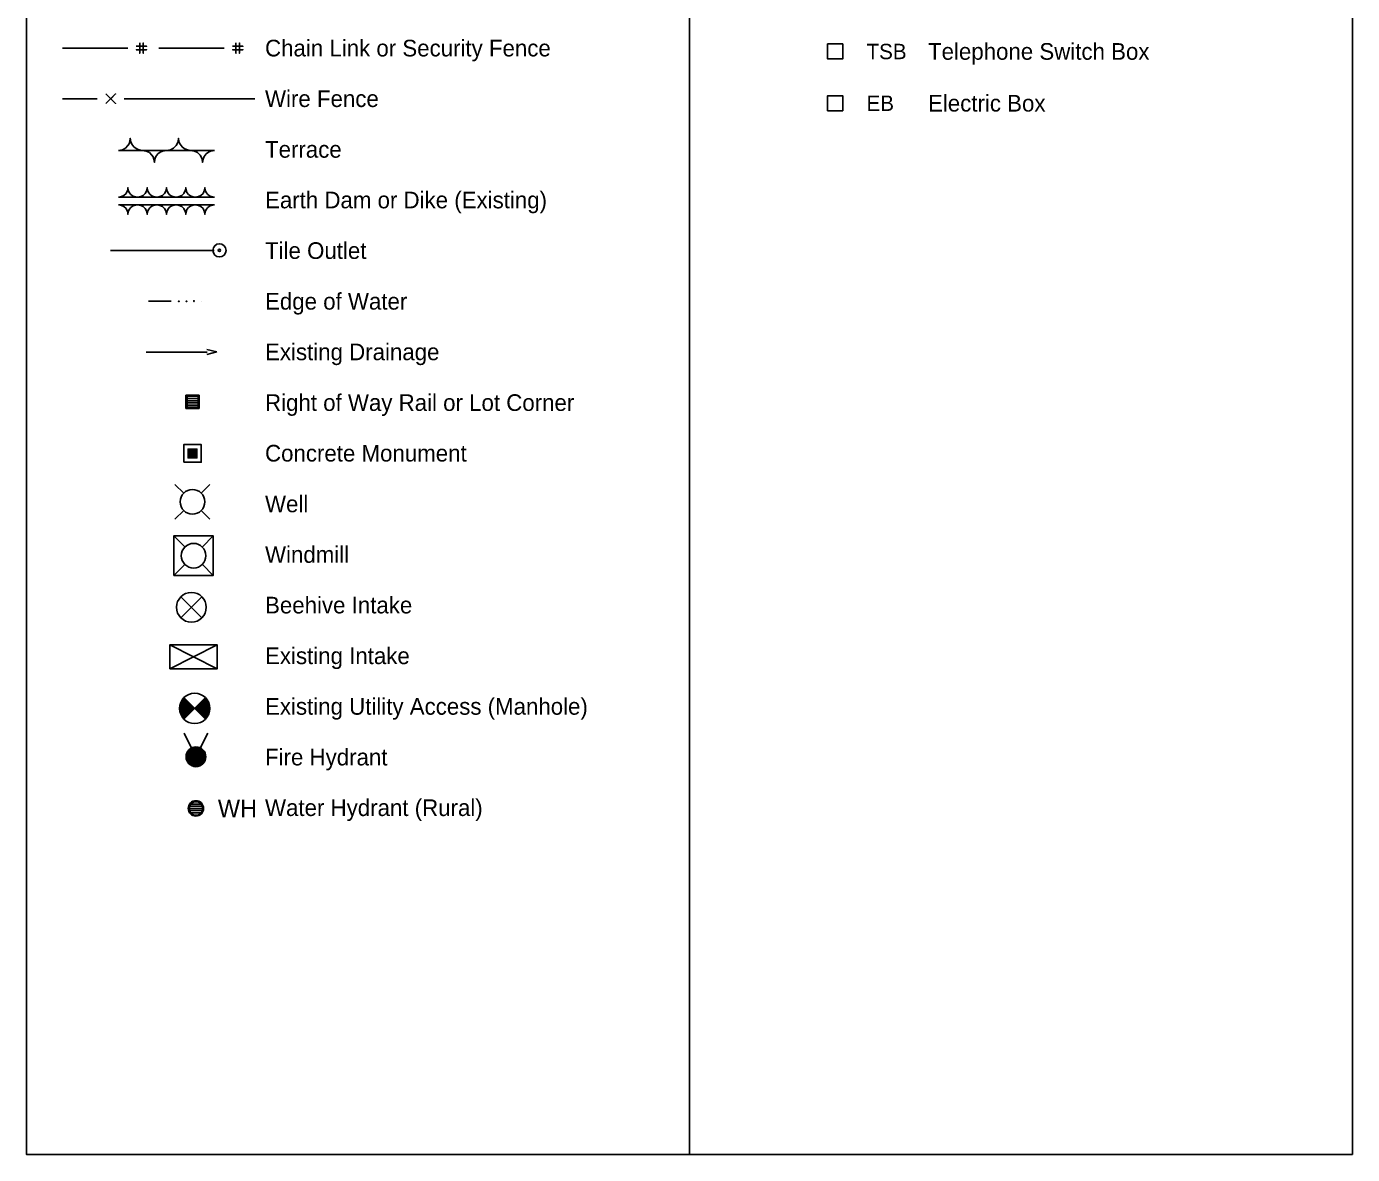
# Model space of a CAD drawing. Extents: x 6082259 to 6083454, y 5964102 to 5966092.
# Drawn here: x 6082259 to 6083454, y 5964102 to 5965119 of the extents above; entities that cross this region are included whole.
import ezdxf

# ---------------------------------------------------------------- set-up
doc = ezdxf.new("R2010")
doc.units = 0
for name, color, linetype in [('Default', 7, 'Continuous'), ('dsnTextShtTitle', 7, 'Continuous'), ('ShtPlotIdentification', 7, 'Continuous')]:
    doc.layers.add(name, color=color, linetype=linetype)

msp = doc.modelspace()

# ---------------------------------------------------------------- linework, layer by layer
at = {"layer": 'Default'}
for points in [[(6082259, 5966092.2), (6082856.5, 5966092.2), (6082856.5, 5964102.2), (6082259, 5964102.2)], [(6082856.5, 5966092.2), (6083454, 5966092.2), (6083454, 5964102.2), (6082856.5, 5964102.2)]]:
    msp.add_lwpolyline(points, close=True, dxfattribs=at)
at = {"layer": 'ShtPlotIdentification'}
for p, q in [((6082334.7, 5964916.8), (6082428.3, 5964916.8)), ((6082369, 5964871.1), (6082389.5, 5964871.1)), ((6082410, 5964871.1), (6082410, 5964871.1)), ((6082417, 5964871.3), (6082417, 5964871.3)), ((6082367, 5964825.4), (6082421.8, 5964825.4)), ((6082421.5, 5964827.8), (6082430.6, 5964825.5)), ((6082430.6, 5964825.5), (6082421.5, 5964823.2)), ((6082392.8, 5964706.1), (6082400.7, 5964698.3)), ((6082416.5, 5964698.3), (6082424.4, 5964706.1)), ((6082392.8, 5964674.6), (6082400.7, 5964682.5)), ((6082416.5, 5964682.5), (6082424.4, 5964674.6)), ((6082391.8, 5964659.7), (6082401.7, 5964649.7)), ((6082417.5, 5964649.7), (6082427.4, 5964659.7)), ((6082391.8, 5964624), (6082401.7, 5964634)), ((6082417.5, 5964634), (6082427.4, 5964624)), ((6082398.2, 5964585.8), (6082417.1, 5964604.7)), ((6082398.2, 5964604.7), (6082417.1, 5964585.8)), ((6082400.9, 5964494.5), (6082420.3, 5964513.9)), ((6082400.9, 5964513.9), (6082420.3, 5964494.5)), ((6082401, 5964482), (6082411.7, 5964460.6)), ((6082411.7, 5964460.6), (6082422.4, 5964482))]:
    msp.add_line(p, q, dxfattribs=at)
for points in [[(6082291.6, 5965099.3), (6082350.5, 5965099.3)], [(6082361.1, 5965104), (6082361.1, 5965094.6), (6082361.1, 5965097.8), (6082358, 5965097.8), (6082367.3, 5965097.8), (6082364.2, 5965097.8), (6082364.2, 5965094.6), (6082364.2, 5965104), (6082364.2, 5965100.9), (6082367.3, 5965100.9), (6082358, 5965100.9)], [(6082378.3, 5965099.3), (6082437.2, 5965099.3)], [(6082447.8, 5965104), (6082447.8, 5965094.6), (6082447.8, 5965097.8), (6082444.7, 5965097.8), (6082454, 5965097.8), (6082450.9, 5965097.8), (6082450.9, 5965094.6), (6082450.9, 5965104), (6082450.9, 5965100.9), (6082454, 5965100.9), (6082444.7, 5965100.9)], [(6082987.8, 5965089.5), (6082987.8, 5965089.5), (6082994.6, 5965089.5), (6082994.6, 5965103.1), (6082981, 5965103.1), (6082981, 5965089.5), (6082987.8, 5965089.5)], [(6082330.6, 5965049.4), (6082339.3, 5965058), (6082334.9, 5965053.7), (6082339.3, 5965049.4), (6082330.6, 5965058)], [(6082291.6, 5965053.7), (6082322.8, 5965053.7)], [(6082347.1, 5965053.7), (6082464.9, 5965053.7)], [(6082987.8, 5965042.8), (6082987.8, 5965042.8), (6082994.6, 5965042.8), (6082994.6, 5965056.4), (6082981, 5965056.4), (6082981, 5965042.8), (6082987.8, 5965042.8)], [(6082341.8, 5965007.1), (6082345.4, 5965007.7), (6082348.1, 5965009.2), (6082350.5, 5965011.5), (6082351.5, 5965013.1), (6082352.2, 5965015.2), (6082352.6, 5965018), (6082353, 5965014.9), (6082354, 5965012.6), (6082355.9, 5965010.2), (6082357.9, 5965008.7), (6082359.8, 5965007.8), (6082363.4, 5965007.1)], [(6082385.1, 5965007.1), (6082388.7, 5965007.7), (6082391.5, 5965009.2), (6082393.8, 5965011.5), (6082394.8, 5965013.1), (6082395.6, 5965015.2), (6082396, 5965018), (6082396.4, 5965014.9), (6082397.4, 5965012.6), (6082399.2, 5965010.2), (6082401.2, 5965008.7), (6082403.2, 5965007.8), (6082406.8, 5965007.1)], [(6082341.8, 5965007.1), (6082428.5, 5965007.1)], [(6082363.4, 5965007.1), (6082367, 5965006.5), (6082369.8, 5965005.1), (6082372.1, 5965002.8), (6082373.1, 5965001.2), (6082373.9, 5964999.1), (6082374.3, 5964996.3), (6082374.7, 5964999.3), (6082375.7, 5965001.7), (6082377.5, 5965004), (6082379.6, 5965005.6), (6082381.5, 5965006.5), (6082385.1, 5965007.1)], [(6082406.8, 5965007.1), (6082410.4, 5965006.5), (6082413.1, 5965005.1), (6082415.5, 5965002.8), (6082416.5, 5965001.2), (6082417.3, 5964999.1), (6082417.6, 5964996.3), (6082418.1, 5964999.3), (6082419, 5965001.7), (6082420.9, 5965004), (6082422.9, 5965005.6), (6082424.8, 5965006.5), (6082428.5, 5965007.1)], [(6082341.8, 5964965), (6082344.6, 5964965.5), (6082346.8, 5964966.6), (6082348.7, 5964968.4), (6082349.5, 5964969.7), (6082350.2, 5964971.4), (6082350.4, 5964973.6), (6082350.8, 5964971.2), (6082351.6, 5964969.3), (6082353, 5964967.4), (6082354.7, 5964966.2), (6082356.2, 5964965.5), (6082359.1, 5964965)], [(6082341.8, 5964965), (6082428.5, 5964965)], [(6082359.1, 5964965), (6082362, 5964965.5), (6082364.2, 5964966.6), (6082366.1, 5964968.4), (6082366.9, 5964969.7), (6082367.5, 5964971.4), (6082367.8, 5964973.6), (6082368.1, 5964971.2), (6082368.9, 5964969.3), (6082370.4, 5964967.4), (6082372, 5964966.2), (6082373.5, 5964965.5), (6082376.5, 5964965)], [(6082376.5, 5964965), (6082379.3, 5964965.5), (6082381.5, 5964966.6), (6082383.4, 5964968.4), (6082384.2, 5964969.7), (6082384.8, 5964971.4), (6082385.1, 5964973.6), (6082385.5, 5964971.2), (6082386.3, 5964969.3), (6082387.7, 5964967.4), (6082389.3, 5964966.2), (6082390.9, 5964965.5), (6082393.8, 5964965)], [(6082393.8, 5964965), (6082396.6, 5964965.5), (6082398.9, 5964966.6), (6082400.7, 5964968.4), (6082401.5, 5964969.7), (6082402.2, 5964971.4), (6082402.5, 5964973.6), (6082402.8, 5964971.2), (6082403.6, 5964969.3), (6082405.1, 5964967.4), (6082406.7, 5964966.2), (6082408.2, 5964965.5), (6082411.1, 5964965)], [(6082411.1, 5964965), (6082414, 5964965.5), (6082416.2, 5964966.6), (6082418.1, 5964968.4), (6082418.9, 5964969.7), (6082419.5, 5964971.4), (6082419.8, 5964973.6), (6082420.1, 5964971.2), (6082420.9, 5964969.3), (6082422.4, 5964967.4), (6082424, 5964966.2), (6082425.5, 5964965.5), (6082428.5, 5964965)], [(6082341.8, 5964958), (6082359.1, 5964958)], [(6082341.8, 5964958), (6082344.6, 5964957.5), (6082346.8, 5964956.4), (6082348.7, 5964954.6), (6082349.5, 5964953.3), (6082350.2, 5964951.6), (6082350.4, 5964949.4), (6082350.8, 5964951.8), (6082351.6, 5964953.7), (6082353, 5964955.6), (6082354.7, 5964956.8), (6082356.2, 5964957.5), (6082359.1, 5964958)], [(6082359.1, 5964958), (6082376.4, 5964958)], [(6082359.1, 5964958), (6082362, 5964957.5), (6082364.2, 5964956.4), (6082366.1, 5964954.6), (6082366.9, 5964953.3), (6082367.5, 5964951.6), (6082367.8, 5964949.4), (6082368.1, 5964951.8), (6082368.9, 5964953.7), (6082370.4, 5964955.6), (6082372, 5964956.8), (6082373.5, 5964957.5), (6082376.4, 5964958)], [(6082376.5, 5964958), (6082393.8, 5964958)], [(6082376.5, 5964958), (6082379.3, 5964957.5), (6082381.5, 5964956.4), (6082383.4, 5964954.6), (6082384.2, 5964953.3), (6082384.8, 5964951.6), (6082385.1, 5964949.4), (6082385.5, 5964951.8), (6082386.3, 5964953.7), (6082387.7, 5964955.6), (6082389.3, 5964956.8), (6082390.9, 5964957.5), (6082393.8, 5964958)], [(6082393.8, 5964958), (6082411.1, 5964958)], [(6082393.8, 5964958), (6082396.6, 5964957.5), (6082398.9, 5964956.4), (6082400.7, 5964954.6), (6082401.5, 5964953.3), (6082402.2, 5964951.6), (6082402.5, 5964949.4), (6082402.8, 5964951.8), (6082403.6, 5964953.7), (6082405.1, 5964955.6), (6082406.7, 5964956.8), (6082408.2, 5964957.5), (6082411.1, 5964958)], [(6082411.1, 5964958), (6082428.5, 5964958)], [(6082411.1, 5964958), (6082414, 5964957.5), (6082416.2, 5964956.4), (6082418.1, 5964954.6), (6082418.9, 5964953.3), (6082419.5, 5964951.6), (6082419.8, 5964949.4), (6082420.1, 5964951.8), (6082420.9, 5964953.7), (6082422.4, 5964955.6), (6082424, 5964956.8), (6082425.5, 5964957.5), (6082428.5, 5964958)], [(6082403.7, 5964775.6), (6082403.7, 5964785.5), (6082413.6, 5964785.5), (6082413.6, 5964775.6), (6082403.7, 5964775.6), (6082403.7, 5964777.5), (6082413.6, 5964777.5), (6082413.6, 5964779.5), (6082403.7, 5964779.5), (6082403.7, 5964781.5), (6082413.6, 5964781.5), (6082413.6, 5964783.5), (6082403.7, 5964783.5)], [(6082400.7, 5964726), (6082400.7, 5964741.9), (6082416.5, 5964741.9), (6082416.5, 5964726), (6082400.7, 5964726)], [(6082404.6, 5964730), (6082404.6, 5964737.9), (6082412.6, 5964737.9), (6082412.6, 5964730), (6082404.6, 5964730), (6082405.6, 5964731), (6082405.6, 5964736.9), (6082411.6, 5964736.9), (6082411.6, 5964731), (6082406.6, 5964731), (6082406.6, 5964735.9), (6082410.6, 5964735.9), (6082410.6, 5964732), (6082407.6, 5964732), (6082407.6, 5964734.9), (6082409.6, 5964734.9), (6082409.6, 5964733), (6082408.6, 5964733), (6082408.6, 5964734)], [(6082388.2, 5964540), (6082431, 5964561.4), (6082431, 5964540), (6082388.2, 5964561.4)], [(6082400.7, 5964495.3), (6082401.2, 5964495.3), (6082402.2, 5964496.3), (6082400.2, 5964496.3), (6082399.2, 5964497.3), (6082403.2, 5964497.3), (6082404.2, 5964498.3), (6082398.7, 5964498.3), (6082398.2, 5964499.3), (6082405.1, 5964499.3), (6082406.1, 5964500.3), (6082398.2, 5964500.3), (6082397.7, 5964501.2), (6082407.1, 5964501.2), (6082408.1, 5964502.2), (6082397.7, 5964502.2), (6082397.2, 5964503.2), (6082409.1, 5964503.2), (6082410.1, 5964504.2), (6082397.2, 5964504.2), (6082397.2, 5964505.2), (6082409.1, 5964505.2), (6082408.1, 5964506.2), (6082397.7, 5964506.2), (6082397.7, 5964507.2), (6082407.1, 5964507.2), (6082406.1, 5964508.2), (6082397.7, 5964508.2), (6082398.2, 5964509.2), (6082405.1, 5964509.2), (6082404.2, 5964510.2), (6082398.7, 5964510.2), (6082399.2, 5964511.1), (6082403.2, 5964511.1), (6082402.2, 5964512.1), (6082399.7, 5964512.1), (6082400.7, 5964513.1), (6082401.2, 5964513.1), (6082410.1, 5964504.2), (6082401.2, 5964495.3), (6082400.7, 5964495.3), (6082399.2, 5964497.3), (6082397.7, 5964501.2), (6082397.2, 5964505.2), (6082398.2, 5964509.2), (6082400.7, 5964513.1)], [(6082420.5, 5964495.3), (6082420, 5964495.3), (6082419, 5964496.3), (6082421, 5964496.3), (6082422, 5964497.3), (6082418, 5964497.3), (6082417, 5964498.3), (6082422.5, 5964498.3), (6082423, 5964499.3), (6082416, 5964499.3), (6082415, 5964500.3), (6082423, 5964500.3), (6082423.5, 5964501.2), (6082414.1, 5964501.2), (6082413.1, 5964502.2), (6082423.5, 5964502.2), (6082424, 5964503.2), (6082412.1, 5964503.2), (6082411.1, 5964504.2), (6082424, 5964504.2), (6082424, 5964505.2), (6082412.1, 5964505.2), (6082413.1, 5964506.2), (6082423.5, 5964506.2), (6082423.5, 5964507.2), (6082414.1, 5964507.2), (6082415, 5964508.2), (6082423.5, 5964508.2), (6082423, 5964509.2), (6082416, 5964509.2), (6082417, 5964510.2), (6082422.5, 5964510.2), (6082422, 5964511.1), (6082418, 5964511.1), (6082419, 5964512.1), (6082421.5, 5964512.1), (6082420.5, 5964513.1), (6082420, 5964513.1), (6082411.1, 5964504.2), (6082420, 5964495.3), (6082420.5, 5964495.3), (6082422, 5964497.3), (6082423.5, 5964501.2), (6082424, 5964505.2), (6082423, 5964509.2), (6082420.5, 5964513.1)], [(6082413.2, 5964469), (6082410.2, 5964469), (6082406.3, 5964467.1), (6082404.3, 5964464.6), (6082403.3, 5964461.1), (6082403.8, 5964457.7), (6082406.3, 5964454.2), (6082408.7, 5964452.7), (6082411.7, 5964452.2), (6082414.7, 5964452.7), (6082417.7, 5964454.7), (6082419.6, 5964457.7), (6082420.1, 5964460.6), (6082419.6, 5964463.6), (6082418.2, 5964466.1), (6082415.7, 5964468.1), (6082413.2, 5964469), (6082416.7, 5964467.6), (6082407.3, 5964467.6), (6082405.3, 5964466.1), (6082418.2, 5964466.1), (6082419.1, 5964464.6), (6082404.3, 5964464.6), (6082403.8, 5964463.1), (6082419.6, 5964463.1), (6082420.1, 5964461.6), (6082403.3, 5964461.6), (6082403.3, 5964460.1), (6082420.1, 5964460.1), (6082419.6, 5964458.6), (6082403.8, 5964458.6), (6082404.3, 5964457.2), (6082419.1, 5964457.2), (6082418.2, 5964455.7), (6082405.3, 5964455.7), (6082406.3, 5964454.2), (6082417.2, 5964454.2), (6082414.7, 5964452.7), (6082408.7, 5964452.7)], [(6082413.7, 5964420), (6082409.7, 5964420), (6082406.8, 5964418), (6082405.8, 5964416), (6082405.8, 5964412.1), (6082406.8, 5964410.1), (6082409.7, 5964408.1), (6082413.7, 5964408.1), (6082416.7, 5964410.1), (6082417.7, 5964412.1), (6082417.7, 5964416), (6082416.7, 5964418), (6082413.7, 5964420), (6082416.7, 5964418), (6082406.8, 5964418), (6082405.8, 5964416), (6082417.7, 5964416), (6082417.7, 5964414.1), (6082405.8, 5964414.1), (6082405.8, 5964412.1), (6082417.7, 5964412.1), (6082416.7, 5964410.1), (6082406.8, 5964410.1)]]:
    msp.add_lwpolyline(points, dxfattribs=at)
for points in [[(6082402.7, 5964774.6), (6082402.7, 5964786.5), (6082414.6, 5964786.5), (6082414.6, 5964774.6)], [(6082391.8, 5964624), (6082391.8, 5964659.7), (6082427.4, 5964659.7), (6082427.4, 5964624)], [(6082388.2, 5964540), (6082388.2, 5964561.4), (6082431, 5964561.4), (6082431, 5964540)]]:
    msp.add_lwpolyline(points, close=True, dxfattribs=at)
for centre, radius in [((6082432.9, 5964917), 5.94), ((6082432.9, 5964917), 0.991), ((6082396.3, 5964871.1), 0.342), ((6082403.2, 5964871.1), 0.342), ((6082410, 5964871.3), 0.342), ((6082408.6, 5964690.4), 11.1), ((6082409.6, 5964641.8), 11.1), ((6082407.6, 5964595.3), 13.4), ((6082410.6, 5964504.2), 13.7), ((6082411.7, 5964460.6), 8.92), ((6082411.7, 5964414.1), 6.93)]:
    msp.add_circle(centre, radius, dxfattribs=at)

# ---------------------------------------------------------------- texts
at = {"layer": 'dsnTextShtTitle'}
for s, p in [('Chain Link or Security Fence', (6082474, 5965091.8)), ('Telephone Switch Box', (6083071.5, 5965088.8)), ('Wire Fence', (6082474, 5965046.2)), ('Electric Box', (6083071.5, 5965042.1)), ('Terrace', (6082474, 5965000.5)), ('Earth Dam or Dike (Existing)', (6082474, 5964954.9)), ('Tile Outlet', (6082474, 5964909.3)), ('Edge of Water', (6082474, 5964863.6)), ('Existing Drainage', (6082474, 5964818)), ('Right of Way Rail or Lot Corner', (6082474, 5964772.3)), ('Concrete Monument', (6082474, 5964726.7)), ('Windmill', (6082474, 5964635.4)), ('Beehive Intake', (6082474, 5964589.8)), ('Existing Intake', (6082474, 5964544.1)), ('Existing Utility Access (Manhole)', (6082474, 5964498.5)), ('Fire Hydrant', (6082474, 5964452.8)), ('Water Hydrant (Rural)', (6082474, 5964407.2))]:
    msp.add_text(s, height=15, dxfattribs=at).set_placement(p)
at = {"layer": 'ShtPlotIdentification'}
for s, height, p in [('TSB', 13.87, (6083016.1, 5965089.3)), ('EB', 13.87, (6083016.1, 5965042.7)), ('Well', 15, (6082474, 5964681)), ('WH', 15.85, (6082431.5, 5964406.1))]:
    msp.add_text(s, height=height, dxfattribs=at).set_placement(p)

doc.saveas('drawing.dxf')
